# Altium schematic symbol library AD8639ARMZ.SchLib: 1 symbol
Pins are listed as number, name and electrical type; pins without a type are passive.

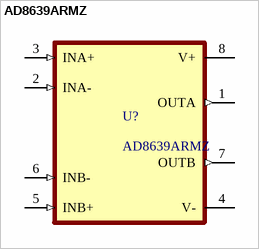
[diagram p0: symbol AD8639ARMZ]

## AD8639ARMZ
designator U?
Low offset voltage: 9 μV maximum Offset drift: 0.04 μV/°C maximum Rail-to-rail output swing 5 V to 16 V single-supply or ±2.5 V to ±8 V dual-supply; MF: Analog Devices; MP: AD8639ARZ
footprint AD8639ARMZ
pins: 1 OUTA (out), 2 INA- (in), 3 INA+ (in), 4 V- (power), 5 INB+ (in), 6 INB- (in), 7 OUTB (out), 8 V+ (power)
